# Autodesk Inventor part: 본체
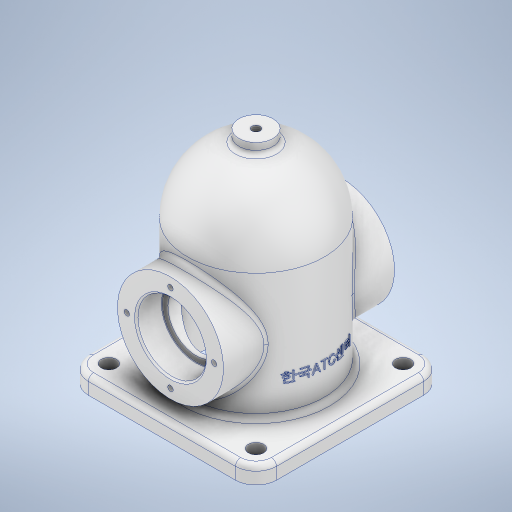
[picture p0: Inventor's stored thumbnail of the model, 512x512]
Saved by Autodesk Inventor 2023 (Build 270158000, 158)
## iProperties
Created: 2025-04
Part Number: 본체
Material: 알루미늄 6061
Document SubType Name: Modeling
Designer: User
Density: 2.7 g/cm^3
Appearance: 알루미늄 - 평지
Mass: 865.986 g
Surface Area: 800.738 cm^2
Volume: 320.736 cm^3
Author: User
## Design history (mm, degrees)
sketch "스케치1"
  geometry: L1 (0, -43.4)-(0, 43.4) reference; L2 (-43.4, 0)-(43.4, 0) reference; C1 r 31 at (0, 0); 1 further point
  constraints: 1 centre point, 1 coincident
  dimensions: "d0" = 62 diameter of C1
extrude "돌출1" new body sketch "스케치1" stored distance "d1" = 100; taper "d2" = 0 deg
node "작업 평면1"
sketch "스케치2"
  geometry: L1 (-55, 55)-(55, 55); L2 (55, 55)-(55, -55); L3 (55, -55)-(-55, -55); L4 (-55, -55)-(-55, 55); L5 (-55, 55)-(55, -55); L6 (55, 55)-(-55, -55); 1 further point
  constraints: 12 end point, 2 midpoint, 2 parallel, 1 horizontal, 1 perpendicular
  dimensions: "d4" = 110 distance of L3.end L1.start; "d5" = 110 distance of L2.end L3.end
extrude "돌출2" join sketch "스케치2" distance "d6" = 10; taper "d7" = 0 deg
sketch "스케치3"
  geometry: C1 r 40 at (0, 0); 1 further point
  constraints: 1 centre point, 1 coincident
  dimensions: "d8" = 80 diameter of C1
extrude "돌출3" join sketch "스케치3" distance "d9" = 84; taper "d10" = 0 deg
sketch "스케치4"
  geometry: L1 (-64.8, 0)-(52.8, 0) reference; L2 (0, -77)-(0, 77) reference; L3 (36, -40)-(36, 40) reference; L4 (36, -40)-(36, 0); L5 (36, 0)-(76, 0); A1 r 40 centre (36, 0) between (36, -40) and (76, 0); 2 further points
  constraints: 4 end point, 2 collinear, 2 point on circle, 1 centre point, 1 midpoint, 1 point on line
  dimensions: "d11" = 40 radius of A1
revolve "회전1" sketch "스케치4" stored, may be unused: angle "d12" = 360 deg
sketch "스케치5"
  geometry: C1 r 10 at (0, 0); 1 further point
  constraints: 1 centre point, 1 coincident
  dimensions: "d13" = 20 diameter of C1
extrude "돌출4" join sketch "스케치5" distance "d14" = 129; taper "d15" = 0 deg
sketch "스케치6"
  geometry: L1 (-73.8, 0)-(106.8, 0) reference; L2 (0, -77)-(0, 77) reference; L3 (36, -40)-(36, 40) reference; L4 (68, 0)-(-48, 0); L5 (-48, -55)-(-48, 55) reference; L6 (36, -32)-(-48, -32); L7 (-48, -32)-(-48, 0); A1 r 32 centre (36, 0) between (36, -32) and (68, 0); 2 further points
  constraints: 6 end point, 2 midpoint, 2 point on circle, 2 point on line, 1 centre point, 1 horizontal, 1 perpendicular
  dimensions: "d16" = 32 radius of A1
revolve "회전2" sketch "스케치6" stored, may be unused: angle "d17" = 360 deg
sketch "스케치7"
  geometry: L1 (-73.8, 0)-(106.8, 0) reference; L2 (0, -77)-(0, 77) reference; L3 (31, 50)-(-31, 50) reference; L4 (0, 50)-(20, 50); L5 (20, 50)-(20, 35); L6 (20, 35)-(0, 35); L7 (0, 35)-(0, 50); L8 (0, 35)-(16.5, 35); L9 (16.5, 35)-(16.5, -35); L10 (16.5, -35)-(0, -35); L11 (0, -35)-(0, 35); L12 (-31, -50)-(31, -50) reference; L13 (0, -35)-(20, -35); L14 (20, -35)-(20, -50); L15 (20, -50)-(0, -50); L16 (0, -50)-(0, -35); 5 further points
  constraints: 24 end point, 6 parallel, 4 symmetric about line, 3 horizontal, 3 perpendicular, 1 midpoint, 1 point on line
  dimensions: "d18" = 40 diameter of L4.end L2; "d19" = 33 diameter of L8.end L2; "d20" = 15 distance of L4.end L5.end
revolve "회전3" sketch "스케치7" stored, may be unused: angle "d21" = 360 deg
sketch "스케치8"
  geometry: L1 (-77, 0)-(77, 0) reference; L2 (0, -73.8)-(0, 106.8) reference; 2 further points
  constraints: 1 point on line
  dimensions: "d22" = 25.5 distance of point (0, 0) point (0, 25.5)
hole "구멍1" sketch "스케치8" at (0, 25.5) diameter "d23" = 3.242; stored, may be unused: countersink angle "d27" = 90 deg, drill point angle "d29" = 118 deg; dims "d24" = 8, "d25" = 4, "d26" = 2, "d28" = 10
sketch "스케치9"
  geometry: L1 (43, 43)-(-43, 43); L2 (-43, 43)-(-43, -43); L3 (-43, -43)-(43, -43); L4 (43, -43)-(43, 43); L5 (43, 43)-(-43, -43); L6 (-43, 43)-(43, -43); L7 (0, -77)-(0, 77) reference; L8 (-77, 0)-(77, 0) reference; C1 r 4.5 at (43, 43); C2 r 4.5 at (43, -43); C3 r 4.5 at (-43, 43); C4 r 4.5 at (-43, -43); 1 further point
  constraints: 12 end point, 4 centre point, 3 symmetric about line, 2 midpoint, 2 parallel, 1 coincident, 1 horizontal, 1 perpendicular, 3 other
  dimensions: "d33" = 86 distance of L3.end L1.start; "d34" = 86 distance of L2.end L3.end; "d35" = 9 diameter of C1
extrude "돌출5" cut sketch "스케치9" distance "d36" = 10; taper "d37" = 0 deg
sketch "스케치10"
  geometry: 1 further point
hole "구멍2" sketch "스케치10" at (0, 0) diameter "d38" = 4.917; stored, may be unused: countersink angle "d42" = 90 deg, drill point angle "d44" = 0 deg; dims "d39" = 20, "d40" = 4, "d41" = 2, "d43" = 25
chamfer "모따기1" distance "d45" = 1; stored, may be unused: second distance "d46" = 2, angle "d47" = 45 deg
fillet "모깎기1" dims "d48" = 12
fillet "모깎기2" dims "d49" = 0.3
fillet "모깎기3" dims "d50" = 3
fillet "모깎기4" dims "d51" = 3
node "작업 평면2"
sketch "스케치11"
  geometry: L1 (-73.8, 0)-(106.8, 0) reference; L2 (0, -77)-(0, 77) reference; L3 (-48, 43)-(-48, -43) reference; 2 further points
  constraints: 1 point on line, 1 other
  dimensions: "d53" = 30 distance from line of L3 point (-18, 0)
feature "엠보싱1" sketch "스케치11" dims "d54" = 0.5, "d55" = 0
node "솔리드1"
pattern_circular "원형 패턴1" dims angle "d31" = 360 deg
mirror "미러1"
feature "A9D066F2-1C7D-4E18-AEED-F7BC21143FA4" dims "d23" = 3.242, "d24" = 8, "d25" = 4, "d26" = 2, "d27" = 90 deg, "d28" = 10, "d29" = 118 deg
other parameters: "d3" = -48
